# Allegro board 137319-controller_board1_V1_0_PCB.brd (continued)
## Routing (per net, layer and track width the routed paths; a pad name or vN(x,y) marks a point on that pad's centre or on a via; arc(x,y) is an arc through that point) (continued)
PTC31: length 7.4
  TOP w0.127: 27.3,42.42 27.83,42.95 27.83,43.85 U2.W5
  TOP w0.152: D1.1 25.15,38.99 25.15,40.26 27.3,42.42
PTD0: length 5.5
  TOP w0.127: 37.84,42.42 U2.Y17
  TOP w0.152: R20.1 39.62,40.01 37.84,41.79 37.84,42.42
PTD4: length 7.3
  TOP w0.127: U2.W19 39.85,43.85 40.61,43.85 41.27,43.18
  TOP w0.152: 41.27,43.18 41.78,42.67 41.78,39.62 R21.1
PTD5: length 6.6
  TOP w0.127: 41.27,43.69 40.71,44.25 U2.W20
  TOP w0.152: 41.27,43.69 42.16,42.8 R18.1
PTD7: length 11.3
  TOP w0.127: U2.V19 39.85,45.46 40.51,45.46 41.27,44.7
  TOP w0.152: R22.1 46.1,41.15 44.45,42.8 43.17,42.8 41.27,44.7
PTD8: length 10.6
  TOP w0.127: U2.U17 37.84,45.85 v1(38.24,45.45)
  BOTTOM w0.152: v1(38.24,45.45) 38.24,45.33 39.37,44.2 41.15,44.2 43.56,41.78 43.56,38.99 R23.1
RCON0: length 19.5
  TOP w0.127: U2.M20 40.47,49.85 41.2,49.85 41.27,49.78
  TOP w0.152: RA2.6 44.35,45.09 44.3,45.03 43.36,45.03 v2(42.8,45.59) 41.91,46.48 41.91,49.15 41.27,49.78 ; 50.52,44.83 v2(51.69,44.83)
  ART04 w0.127: v2(42.8,45.59) 43.43,44.96 44.96,44.96 45.89,45.89 50.63,45.89 v2(51.69,44.83)
RCON1: length 21
  TOP w0.127: 41.27,49.15 40.98,49.45 39.85,49.45 U2.M19
  TOP w0.152: S1.7 v2(51.69,43.56) ; 41.27,49.15 41.53,48.9 41.53,45.34 v2(42.8,44.07) 43.36,44.63 44.3,44.63 44.35,44.58 44.98,44.58
  ART04 w0.127: v2(51.69,43.56) 46.1,43.56 45.05,44.62 43.35,44.62 v2(42.8,44.07)
RCON2: length 21.8
  TOP w0.127: U2.M17 37.84,49.85 v1(38.24,49.45)
  TOP w0.152: S1.8 v2(51.69,42.29) ; RA2.8 v2(44.07,44.07)
  ART04 w0.127: v1(38.24,49.45) 38.64,49.05 40.86,49.05 41.91,48.01 41.91,44.19 42.66,43.43 43.43,43.43 v2(44.07,44.07) 44.83,44.07 45.72,43.18 50.8,43.18 v2(51.69,42.29)
RCON3: length 9.4
  TOP w0.127: U2.M16 v1(37.44,49.45)
  TOP w0.152: RA3.5 v2(44.07,51.18)
  BOTTOM w0.127: v1(37.44,49.45) 37.84,49.85 37.84,50.54 38.1,50.8 41.27,50.8
  BOTTOM w0.152: v2(44.07,51.18) 43.43,50.55 41.66,50.55 41.4,50.8 41.27,50.8
RCON4: length 9
  TOP w0.127: U2.L16 v1(37.44,50.25)
  TOP w0.152: RA3.6 44.35,50.67 44.3,50.62 43.44,50.62 v2(42.89,51.18)
  BOTTOM w0.127: 41.27,51.18 37.97,51.18 37.44,50.65 v1(37.44,50.25)
  BOTTOM w0.152: 41.27,51.18 42.67,51.18 42.67,51.18 v2(42.89,51.18)
RCON5: length 24
  TOP w0.127: U2.L17 37.84,50.65 v1(38.24,50.25)
  TOP w0.152: RA1.7 44.35,47.37 44.3,47.42 43.36,47.42 v2(42.8,46.86) ; S1.3 v2(51.69,48.64)
  ART04 w0.127: v2(51.69,48.64) 51.65,48.68 46.27,48.68 45.09,47.5 43.43,47.5 v2(42.8,46.86)
  BOTTOM w0.127: v1(38.24,50.25) 38.64,49.85 39.3,49.85 39.75,49.4 41.27,49.4
  BOTTOM w0.152: v2(42.8,46.86) 43.56,47.62 44.32,47.62 44.7,48.01 44.7,48.64 43.94,49.4 41.27,49.4
RCON6: length 19.8
  TOP w0.127: v1(39.04,50.25) 38.64,50.65 U2.L18
  TOP w0.152: 50.52,47.37 v2(51.69,47.37) ; RA1.8 v2(44.07,46.86)
  ART04 w0.127: v2(44.07,46.86) 44.36,46.57 50.89,46.57 v2(51.69,47.37)
  BOTTOM w0.127: v1(39.04,50.25) 39.28,50.25 39.74,49.78 41.27,49.78
  BOTTOM w0.152: v2(44.07,46.86) 45.09,47.88 45.09,48.9 44.2,49.78 41.27,49.78
RCON7: length 20.1
  TOP w0.127: v1(40.64,50.25) 40.24,50.65 U2.L20
  TOP w0.152: RA2.5 v2(44.07,45.59) ; S1.5 v2(51.69,46.1)
  ART04 w0.127: v2(51.69,46.1) 51.56,46.23 45.72,46.23 45.09,45.59 v2(44.07,45.59)
  BOTTOM w0.127: 41.27,50.16 40.73,50.16 v1(40.64,50.25)
  BOTTOM w0.152: 41.27,50.16 44.58,50.16 45.47,49.28 45.47,46.99 v2(44.07,45.59)
RCON8: length 5.3
  TOP w0.127: 41.27,51.45 U2.K20
  TOP w0.152: 41.27,51.45 41.51,51.45 42.8,50.16 RA3.7
RCON9: length 6.3
  TOP w0.127: U2.K19 39.84,51.05 41.27,51.05
  TOP w0.152: 41.27,51.05 42.67,49.66 RA3.8
RCON10: length 10.6
  TOP w0.127: U2.K18 38.64,51.45 v1(39.04,51.85)
  TOP w0.152: RA4.5 v2(44.07,56.77)
  ART04 w0.127: v1(39.04,51.85) 39.44,52.25 41.07,52.25 41.66,52.83 41.66,53.59 42.67,54.61 43.05,54.61 43.43,54.99 43.43,56.13 v2(44.07,56.77)
  BOTTOM w0.152: R1.1 v2(44.07,56.77)
RCON11: length 15
  TOP w0.127: v1(34.24,59.05) 33.84,58.65 U2.A12
  TOP w0.152: v2(42.8,59.18) 42.8,56.77 43.36,56.21 44.3,56.21 44.35,56.26 RA4.6
  BOTTOM w0.127: 35.38,60.2 v1(34.24,59.05)
  BOTTOM w0.152: 35.38,60.2 35.51,60.33 41.66,60.33 v2(42.8,59.18)
RCON12: length 11.2
  TOP w0.127: v1(38.24,52.65) 37.84,52.25 U2.J17
  TOP w0.152: RA4.7 44.35,55.75 44.3,55.8 43.36,55.8 v2(42.8,55.24)
  ART04 w0.127: v2(42.8,55.24) 40.6,53.05 40,53.05 39.67,53.05 38.64,53.05 v1(38.24,52.65)
  BOTTOM w0.152: R2.1 44.58,55.88 43.43,55.88 v2(42.8,55.24)
RCON13: length 6.8
  TOP w0.127: U2.D19 39.44,56.25 v1(39.84,56.65)
  TOP w0.152: RA4.8 v2(44.07,55.24)
  BOTTOM w0.127: 41.27,55.88 40.9,56.25 40.24,56.25 v1(39.84,56.65)
  BOTTOM w0.152: 41.27,55.88 42.55,54.61 43.43,54.61 v2(44.07,55.24)
RCON14: length 10
  TOP w0.127: v1(39.84,57.45) 39.44,57.05 U2.C19
  TOP w0.152: RA5.5 v2(44.07,53.94)
  ART04 w0.127: v2(44.07,53.94) 44.83,54.7 44.83,56.9 44.41,57.32 42.51,57.32 42.37,57.45 v1(39.84,57.45)
RCON18: length 27
  TOP w0.127: U2.L4 27.84,50.25 v1(28.64,50.25)
  TOP w0.152: RA5.6 44.35,53.43 44.3,53.38 43.36,53.38 v2(42.8,53.94)
  ART03 w0.127: v2(42.8,53.94) 42.71,53.86 36.95,53.86 35.44,55.37 35.44,56.02 35.2,56.25 35.19,56.25 35.18,56.26 31.68,56.26 31.44,56.01 31.44,51.63 30.61,50.8 29.19,50.8 v1(28.64,50.25)
  BOTTOM w0.152: R3.1 44.58,53.34 43.4,53.34 v2(42.8,53.94)
RCON20: length 92.3
  TOP w0.152: v2(42.8,52.42) 43.36,52.98 44.3,52.98 44.35,52.93 RA5.7
  ART04 w0.127: v2(13.06,60.2) 13.06,62.48 11.56,63.98 11.56,65.88 10.79,66.64 10.79,77.34 12.95,79.5 36.83,79.5 38.61,77.72 42.93,77.72 48.64,72.01 48.64,52.7 48.01,52.07 46.23,52.07 45.34,52.96 44.3,52.96 44.3,52.96 43.84,52.96 43.84,52.96 43.34,52.96 v2(42.8,52.42)
  BOTTOM w0.152: R4.1 44.56,52.98 43.36,52.98 v2(42.8,52.42) ; U15.18 v2(13.06,60.2)
RCON21: length 17.2
  TOP w0.127: U2.A17 37.84,58.66 v1(37.44,59.05)
  TOP w0.152: RA5.8 v2(44.07,52.42)
  ART04 w0.127: v1(37.44,59.05) 37.84,58.65 37.84,51.69 38.22,51.31 41.53,51.31 42.04,51.82 43.47,51.82 v2(44.07,52.42)
  BOTTOM w0.152: v2(44.07,52.42) 44.07,52.32 R5.1
RCON22: length 37.7
  TOP w0.152: v2(25.78,39.88) 26.42,40.51 27.43,40.51 27.81,40.13 27.81,38.73 27.3,38.23 RA6.5
  ART03 w0.127: v2(10.92,60.2) 10.92,58.29 11.66,57.56 11.66,52.86 13.34,51.18 17.53,51.18 18.92,49.78 21.34,49.78 24,47.12 24,41.66 v2(25.78,39.88)
  BOTTOM w0.152: v2(10.92,60.2) 12.06,60.2 12.41,60.54 U15.17
RCON30: length 10.2
  TOP w0.127: v1(29.44,46.25) 29.84,46.65 U2.T7
  TOP w0.152: RA6.6 26.8,38.73 v2(27.05,38.99)
  BOTTOM w0.127: 29.84,42.42 29.84,45.85 v1(29.44,46.25)
  BOTTOM w0.152: v2(27.05,38.99) 29.84,41.78 29.84,42.42
RCON31: length 8.4
  TOP w0.127: v1(29.44,44.65) 29.84,45.05 U2.V7
  TOP w0.152: v2(27.05,39.88) 26.29,39.12 RA6.7
  BOTTOM w0.127: v1(29.44,44.65) 29.04,44.25 29.04,42.42
  BOTTOM w0.152: 29.04,42.42 29.04,41.87 v2(27.05,39.88)
RESET_B: length 59.7
  TOP w0.127: U2.T4 27.44,46.65 v1(27.04,46.25)
  TOP w0.152: U18.4 v2(20.83,31.31)
  ART03 w0.127: v2(21.21,46.23) 19.56,44.58 19.56,32.58 v2(20.83,31.31)
  ART04 w0.127: v2(12.83,64.9) 13.97,63.75 13.97,59.83 14.61,59.19 14.61,57.4 13.97,56.77 13.97,53.85 14.61,53.21 14.61,51.44 18.16,47.88 18.16,47.2 19.14,46.23 v2(21.21,46.23)
  BOTTOM w0.127: v1(27.04,46.25) 26.64,45.85 26.07,45.85 22.86,45.85
  BOTTOM w0.152: 13.71,64.9 v2(12.83,64.9) 12.45,65.28 J3.10 ; C34.1 R46.2 v2(21.21,46.23) 21.59,45.85 22.86,45.85
SAFE_MODE_EN_N: length 66
  TOP w0.127: v1(39.04,46.25) 38.64,46.65 U2.T18
  ART03 w0.127: v1(39.04,46.25) 39.44,46.65 41.06,46.65 41.78,47.37 41.78,48.9 42.42,49.53 45.47,49.53 46.1,50.16 47.75,50.16 48.28,50.69 48.28,64.5 47.62,65.15 47.62,76.71 44.58,79.76 36.2,79.76 30.99,84.96 30.99,86.49 30.48,87 27.01,87 J1.15
SDHC1_CD: length 8.4
  TOP w0.127: U2.V15 36.24,45.05 v1(36.64,44.65)
  BOTTOM w0.152: R60.1 R59.1 36.64,40.7 v1(36.64,44.65)
SDHC1_CLK: length 50.8
  TOP w0.152: CN1.5 9.82,22.18 10.54,21.46 17.52,21.46 U7.6 v2(17.85,22.86) ; 43.43,37.72 43.43,34.67 v2(40.64,31.88)
  ART04 w0.127: v2(17.85,22.86) 17.85,26.61 22.86,31.62 27.69,31.62 28.45,30.86 30.23,30.86 31.11,31.75 33.91,31.75 34.46,32.3 40.22,32.3 v2(40.64,31.88)
  BOTTOM w0.152: R56.2 v2(17.85,22.86)
SDHC1_CMD: length 62.6
  TOP w0.127: U2.R17 37.84,47.45 v1(38.24,47.05)
  TOP w0.152: CN1.3 8.68,19.98 9.4,20.7 18.99,20.7 19.75,21.46 U7.4 v2(19.75,22.86)
  ART04 w0.127: v2(19.75,22.86) 19.75,22.92 19.43,23.24 19.43,27.05 22.61,30.23 40.13,30.23 41.53,31.62 41.53,37.08 37.84,40.77 37.84,46.66 v1(38.24,47.05)
  BOTTOM w0.152: R55.2 v2(19.75,22.86)
SDHC1_DAT0: length 61.5
  TOP w0.127: U2.R19 v1(39.84,47.05)
  TOP w0.152: CN1.7 12.96,24.38 13.84,23.5 18.92,23.5 19.62,24.2 U8.1 v2(21.21,24.2)
  ART04 w0.127: v2(21.21,24.2) 20.57,24.83 20.57,26.23 23.42,29.08 40.77,29.08 42.67,30.99 42.67,33.78 43.43,34.54 43.43,37.08 41.53,38.99 41.53,43.43 41.15,43.81 41.15,45.75 v1(39.84,47.05)
  BOTTOM w0.152: R57.2 v2(21.21,24.2)
SDHC1_DAT1: length 59.3
  TOP w0.127: U2.R20 40.24,47.45 v1(40.64,47.05)
  TOP w0.152: CN1.8 12.78,25.48 14.35,27.05 18.8,27.05 19.75,26.1 U8.3 v2(21.21,26.1)
  ART04 w0.127: v2(21.21,26.1) 23.82,28.7 41.02,28.7 43.05,30.73 43.05,33.66 43.81,34.42 43.81,37.21 41.91,39.12 41.91,43.69 41.53,44.07 41.53,46.16 v1(40.64,47.05)
  BOTTOM w0.152: R58.2 v2(21.21,26.1)
SDHC1_DAT2: length 70.7
  TOP w0.127: U2.P20 40.24,48.25 v1(40.64,48.65)
  TOP w0.152: CN1.1 7.87,17.78 9.78,19.68 17.52,19.68 U7.1 R53.2 18.1,17.27 18.67,17.27 v2(18.8,17.14)
  ART04 w0.127: v1(40.64,48.65) 40.24,48.25 38.88,48.25 38.64,48.02 38.64,40.48 41.91,37.21 41.91,31.37 40.39,29.84 22.86,29.84 19.81,26.8 19.81,24.13 20.32,23.62 20.32,21.87 19.56,21.11 19.56,17.91 v2(18.8,17.14)
SDHC1_DAT3: length 69.7
  TOP w0.127: v1(39.04,47.85) 38.64,48.25 U2.P18
  TOP w0.152: CN1.2 8.21,18.88 9.65,20.32 19.18,20.32 19.75,19.75 U7.3 R54.2 v2(20.57,17.53)
  ART04 w0.127: v2(20.57,17.53) 19.94,18.16 19.94,20.95 20.7,21.72 20.7,23.88 20.19,24.38 20.19,26.54 23.11,29.46 40.64,29.46 42.25,31.08 42.25,37.38 41.15,38.48 41.15,43.18 39.44,44.89 39.44,47.45 v1(39.04,47.85)
SPI_CS0_FPGA: length 18.1
  TOP w0.152: 42.16,37.72 42.16,34.29 39.37,31.5 39.37,27.97 38.45,27.05 35.43,27.05 34.54,26.16 34.54,25.13 U11.A10
SPI_CS1_FPGA: length 18.3
  TOP w0.152: U11.A9 34.16,25.55 34.16,26.29 35.31,27.43 38.29,27.43 38.89,28.03 38.89,31.66 41.45,34.21 41.45,37.16 40.89,37.72
SPI_DIN_FPGA: length 17.5
  TOP w0.127: U2.V20 40.24,45.05 v1(40.64,44.65)
  TOP w0.152: R64.1 v2(35.18,30.86)
  ART03 w0.127: v2(35.18,30.86) 35.81,31.5 35.81,33.27 36.79,34.25 36.79,40.81 v1(40.64,44.65)
SPI_DOUT_FPGA: length 19.1
  TOP w0.152: R22.2 46.1,36.32 39.88,30.1 39.88,27.94 38.61,26.67 35.69,26.67 34.95,25.93 U11.A11
SPI_SCK_FPGA: length 18.2
  TOP w0.127: U11.B10 v1(34.55,24.34)
  BOTTOM w0.152: v1(34.55,24.34) 35.39,24.34 42.16,31.11 42.16,34.8 43.43,36.07 43.43,37.59 43.31,37.72
TCK_FPGA: length 31.5
  TOP w0.127: U11.G2 v1(27.35,20.34)
  TOP w0.152: U16.3 48.23,29.24 v2(48.9,28.57)
  ART04 w0.127: v1(27.35,20.34) 26.92,20.77 26.92,23.11 29.84,26.04 30.99,26.04 31.88,26.92 44.04,26.92 46.32,29.21 48.26,29.21 v2(48.9,28.57)
TDI_FPGA: length 26.2
  TOP w0.127: U11.F5 v1(29.75,21.14)
  TOP w0.152: U16.4 v2(47.58,28.57)
  ART04 w0.127: v2(47.58,28.57) 46.23,28.57 44.2,26.54 32.13,26.54 30.15,24.56 30.15,21.54 v1(29.75,21.14)
TDO_FPGA: length 21.4
  TOP w0.127: U11.F6 v1(30.55,21.14)
  TOP w0.152: U16.15 46.28,24.44 v2(45.21,23.37)
  ART04 w0.127: v1(30.55,21.14) 30.95,21.54 30.95,23.7 32.14,24.89 35.94,24.89 37.47,23.37 v2(45.21,23.37)
TMS_FPGA: length 30.8
  TOP w0.127: U11.G1 v1(26.55,20.34)
  TOP w0.152: U16.2 48.88,29.73 v2(48.9,29.72)
  ART04 w0.127: v2(48.9,29.72) 46.29,29.72 43.88,27.3 31.75,27.3 30.86,26.42 28.83,26.42 28.31,25.89 28.31,25.03 26.54,23.27 26.54,20.35 v1(26.55,20.34)
TRACE_D0: length 33.2
  TOP w0.127: v1(28.64,43.85) 28.24,43.45 U2.Y5
  ART04 w0.127: J3.14 7.87,57.28 7.87,53.59 14.48,46.99 17.41,46.99 19.06,45.34 22.35,45.34 23.44,44.25 28.24,44.25 v1(28.64,43.85)
TRACE_D1: length 32.3
  TOP w0.127: U2.Y6 29.04,43.45 v1(28.64,43.05)
  ART04 w0.127: J3.16 7.49,55.12 7.49,53.34 14.73,46.1 14.73,44.45 15.41,43.78 25.18,43.78 25.53,43.43 28.26,43.43 v1(28.64,43.05)
TRACE_D2: length 33.7
  TOP w0.127: U2.V6 v1(28.64,45.45)
  ART04 w0.127: v1(28.64,45.45) U2.V6 29.04,42.76 28.83,42.55 20.57,42.55 19.68,43.43 15.24,43.43 14.35,44.32 14.35,45.85 5.08,55.12 J3.18
TRACE_D3: length 33.9
  TOP w0.127: v1(29.44,45.45) 29.04,45.85 U2.U6
  ART04 w0.127: v1(29.44,45.45) 29.84,45.05 29.84,42.67 29.33,42.16 20.45,42.16 19.56,43.05 14.99,43.05 13.97,44.07 13.97,45.72 7.11,52.58 4.95,52.58
TRACECK: length 30
  TOP w0.127: U2.L3 26.64,50.65 v1(26.24,50.25)
  ART03 w0.127: v1(26.24,50.25) 26.15,50.16 19.05,50.16 17.65,51.56 17.65,52.07 17.02,52.7 14.86,52.7 12.06,55.5 12.06,57.91 11.56,58.42 11.56,60.45 10.54,61.47 6.22,61.47 J3.12
UART_RX0_DEBUG: length 33.6
  TOP w0.127: U2.D14 v1(35.04,56.65)
  ART03 w0.127: v1(35.04,56.65) 35.6,56.65 36.31,57.36 36.31,65.01 36.58,65.28 36.58,78.49 30.08,84.98 30.08,85.92 J1.20
UART_RX1: length 64.8
  TOP w0.127: U2.Y18 38.64,42.42
  TOP w0.152: v2(40.39,40.39) 38.64,42.13 38.64,42.42
  ART03 w0.127: J1.24 39.48,80.52 44.83,80.52 48.39,76.96 48.39,65.41 49.02,64.77 49.02,44.83 44.58,40.39 v2(40.39,40.39)
UART_RX2: length 39.6
  TOP w0.127: v1(39.04,56.65) 38.64,56.25 U2.D18
  BOTTOM w0.127: 41.27,57.05 39.44,57.05 v1(39.04,56.65)
  BOTTOM w0.152: 41.27,57.05 42.45,57.05 43.43,58.04 43.43,66.29 42.8,66.93 41.02,66.93 38.35,69.6 38.35,83.22 36.99,84.58 36.99,87.01 J1.25
UART_RX3: length 88
  TOP w0.127: U11.J9 v1(33.75,17.94)
  ART03 w0.127: v1(33.75,17.94) 34.16,18.35 34.16,18.8 34.54,19.18 36.46,19.18 36.85,19.56 37.08,19.56 38.48,20.95 38.48,24.95 50.55,37.02 50.55,65.28 49.91,65.91 49.91,79.25 48.26,80.9 41.53,80.9 38.99,83.44 38.99,87.01 J1.27
UART_RX4: length 90.3
  TOP w0.127: U11.K10 v1(34.55,17.14)
  TOP w0.152: J1.29 41.01,86.99 41.01,85.59 41.59,85.01 41.61,85.01 41.78,84.84 44.96,84.84 46.23,83.57 v2(46.23,82.3)
  ART03 w0.127: v2(46.23,82.3) 46.86,82.93 48.9,82.93 52.45,79.38 52.45,63.88 53.21,63.12 53.21,37.59 40.01,24.38 40.01,20.32 37.67,17.98 36.76,17.98 36.32,17.54 34.94,17.54 34.55,17.15 v1(34.55,17.14)
UART_RX5: length 82.7
  TOP w0.127: U11.J10 v1(34.55,17.94)
  ART03 w0.127: v1(34.55,17.94) 34.95,18.34 36.24,18.34 36.25,18.34 36.32,18.34 36.55,18.57 36.55,18.64 36.55,18.64 36.55,18.9 36.78,19.14 37.17,19.14 38.86,20.83 38.86,24.8 50.93,36.86 50.93,65.41 50.29,66.04 50.29,79.38 48.39,81.28 44.05,81.28 42,83.33 J1.32
UART_RX6: length 83.6
  TOP w0.127: U11.H13 v1(36.95,18.74)
  ART03 w0.127: v1(36.95,18.74) 37.41,18.74 39.24,20.57 39.24,24.64 52.48,37.87 52.48,62.72 51.69,63.51 51.69,78.96 48.99,81.66 44.29,81.66 43.02,82.93 43.02,87.02 J1.33
UART_RX7: length 81.4
  TOP w0.127: U11.J12 v1(36.15,17.94)
  TOP w0.152: v2(48.13,82.3) 48.13,83.57 46.99,84.71 46.99,86.99 J1.37
  ART03 w0.127: v2(48.13,82.3) 48.99,82.3 52.07,79.22 52.07,63.63 52.83,62.87 52.83,37.72 39.62,24.51 39.62,20.45 37.49,18.31 36.73,18.31 36.35,17.94 v1(36.15,17.94)
UART_RX8: length 79.3
  TOP w0.127: U11.H8 v1(32.95,18.74)
  TOP w0.152: v2(48.51,79.12) 49.01,79.62 49.01,87.01 J1.39
  ART03 w0.127: v2(48.51,79.12) 49.15,78.49 49.15,65.66 49.78,65.02 49.78,37.33 37.72,25.27 37.72,21.21 36.2,19.68 33.9,19.68 v1(32.95,18.74)
UART_RX9: length 30.8
  TOP w0.127: U11.E12 v1(36.15,21.14)
  ART03 w0.127: J2.7 20.49,7.49 24,7.49 27.94,11.43 27.94,13.46 28.55,14.07 28.55,15.09 28.55,15.09 28.55,18.9 28.78,19.14 28.79,19.14 28.83,19.18 32.89,19.18 33.66,19.94 34.95,19.94 v1(36.15,21.14)
UART_RX10: length 21.5
  TOP w0.127: U11.L5 v1(29.75,17.14)
  ART03 w0.127: v1(29.75,17.14) 29.35,16.74 29.35,13.6 28.7,12.95 28.7,11.05 24.13,6.48 21.84,6.48 19.98,4.61 19.98,2.98 J2.10
UART_RX11: length 20.1
  TOP w0.127: U11.L4 v1(29.75,16.34)
  ART03 w0.127: J2.12 21.98,2.98 21.98,4.58 22.86,5.46 24.38,5.46 30.61,11.68 30.61,14.73 30.15,15.19 30.15,15.94 v1(29.75,16.34)
UART_RX12: length 15.6
  TOP w0.152: J2.16 26.01,3.01 26.01,5.15 30.1,9.24 30.1,14.39 U11.N4
UART_RX13: length 12.7
  TOP w0.152: U11.N5 30.48,14.81 30.48,9.08 27,5.6 J2.17
UART_RX14: length 14.3
  TOP w0.152: U11.N7 31.24,14.63 31.24,7.87 30.01,6.64 30.01,3.01 J2.20
UART_RX15: length 15.2
  TOP w0.127: U11.M9 33.76,15.53 33.76,14.22
  TOP w0.152: 33.76,14.22 33.76,8.74 32,6.99 32,3 J2.22
UART_RX16: length 14
  TOP w0.152: U11.N11 34.95,6.96 35.99,5.92 35.99,2.99 J2.26
UART_RX17: length 13
  TOP w0.127: U11.N8 v1(32.95,14.74)
  ART03 w0.127: v1(32.95,14.74) 37,10.69 J2.27
UART_RX18: length 16.6
  TOP w0.127: U11.M8 v1(32.95,15.54)
  ART03 w0.127: v1(32.95,15.54) 37.98,10.51 37.98,3.02 J2.30
UART_RX19: length 16.6
  TOP w0.152: U11.M13 36.96,15.53 36.96,9.44 41.99,4.41 41.99,2.99 J2.32
UART_RX_FROM_FPGA: length 24.7
  TOP w0.127: U2.M3 26.64,49.85 v1(26.24,49.45)
  TOP w0.152: R65.1 30.81,30.53 30.81,31.67 v2(29.97,32.51)
  ART03 w0.127: v2(29.97,32.51) 31.44,33.98 31.44,44.02 31.2,44.25 30.08,44.25 29.84,44.49 29.84,46.41 28,48.25 26.88,48.25 26.64,48.49 26.64,49.05 v1(26.24,49.45)
UART_TX0_DEBUG: length 27.9
  TOP w0.152: R25.1 38.93,65.21 38.93,65.72 v2(39.5,66.29)
  BOTTOM w0.152: J1.19 30.99,87.01 30.99,84.96 37.59,78.36 37.59,68.2 v2(39.5,66.29)
UART_TX1: length 67
  TOP w0.152: 39.62,37.72 40.13,37.72 40.26,37.85 40.26,39.12 40.94,39.8 40.94,40.84 v2(40.39,41.4)
  ART03 w0.127: v2(40.39,41.4) 41.02,40.77 44.42,40.77 48.68,45.03 48.68,64.6 48.01,65.28 48.01,76.83 44.7,80.14 37.86,80.14 J1.22
UART_TX2: length 26.3
  TOP w0.152: R24.1 v2(39.5,65.41)
  BOTTOM w0.152: v2(39.5,65.41) 40.13,66.04 40.13,66.93 37.97,69.09 37.97,81.85 34.99,84.84 34.99,87.01 J1.23
UART_TX3: length 89.5
  TOP w0.127: U11.K13 v1(36.95,17.14)
  TOP w0.152: J1.28 40.56,83.44 44.32,83.44 v2(44.94,84.06)
  ART03 w0.127: v1(36.95,17.14) 37.97,17.14 40.77,19.94 40.77,24.17 54.01,37.42 54.01,63.46 53.21,64.26 53.21,79.75 49.27,83.69 45.34,83.69 44.97,84.06 v2(44.94,84.06)
UART_TX4: length 88
  TOP w0.127: v1(36.15,17.14) 35.35,17.14 U11.K11
  TOP w0.152: v2(43.69,84.07) 41.4,84.07 40,85.48 J1.30
  ART03 w0.127: v2(43.69,84.07) 44.45,83.31 49.11,83.31 52.83,79.59 52.83,64.14 53.63,63.33 53.63,37.5 40.39,24.26 40.39,20.07 37.97,17.65 36.9,17.65 36.39,17.14 v1(36.15,17.14)
UART_TX5: length 85.1
  TOP w0.127: U11.L12 v1(36.15,16.34)
  ART03 w0.127: v1(36.15,16.34) 36.55,16.74 38.2,16.74 41.15,19.68 41.15,24 54.39,37.25 54.39,63.59 53.59,64.39 53.59,79.91 49.43,84.07 45.93,84.07 J1.34
UART_TX6: length 82.2
  TOP w0.127: U11.H9 v1(33.75,18.74)
  TOP w0.152: v2(47.37,79.12) 47.37,83.19 45.01,85.55 45.01,87.01 J1.35
  ART03 w0.127: v2(47.37,79.12) 48.01,79.76 48.86,79.76 49.53,79.09 49.53,65.79 50.16,65.15 50.16,37.18 38.1,25.11 38.1,21.12 36.79,19.81 36.74,19.81 36.36,19.43 34.29,19.43 33.75,18.89 v1(33.75,18.74)
UART_TX7: length 81.2
  TOP w0.127: U11.L13 v1(36.95,16.34)
  ART03 w0.127: v1(36.95,16.34) 38.31,16.34 41.53,19.56 41.53,23.88 54.74,37.08 54.74,63.88 53.98,64.64 53.98,80.02 J1.38
UART_TX8: length 73.6
  TOP w0.127: v1(36.95,21.94) 37.35,21.54 37.35,20.58 37.1,20.33 36.14,20.33 U11.G12
  TOP w0.152: J1.40 50,79.46 v2(48.51,77.98)
  ART03 w0.127: v2(48.51,77.98) 48.77,77.72 48.77,65.53 49.4,64.9 49.4,37.49 37.35,25.44 37.35,22.34 v1(36.95,21.94)
UART_TX9: length 32.2
  TOP w0.127: U11.F12 v1(35.35,21.14)
  ART03 w0.127: J2.5 19,8 23.88,8 27.56,11.68 27.56,13.59 27.75,13.78 27.75,18.73 28.57,19.56 32.77,19.56 33.35,20.15 33.35,20.5 33.59,20.74 34.95,20.74 v1(35.35,21.14)
UART_TX10: length 17.9
  TOP w0.127: U11.M4 v1(28.95,15.54)
  ART03 w0.127: v1(28.95,15.54) 28.95,13.84 28.32,13.21 28.32,11.18 24.13,6.99 21.21,6.99 19,4.78 J2.9
UART_TX11: length 17.2
  TOP w0.127: U11.M5 v1(29.75,15.54)
  ART03 w0.127: J2.11 21,4.62 22.35,5.97 24.26,5.97 29.55,11.26 29.56,11.26 29.88,11.58 29.88,11.6 30.23,11.94 30.23,14.61 29.75,15.08 v1(29.75,15.54)
UART_TX12: length 19.2
  TOP w0.127: U11.K5 v1(30.55,17.14)
  ART03 w0.127: J2.14 24,3 24,4.45 30.95,11.39 30.95,15.7 30.55,16.1 v1(30.55,17.14)
UART_TX13: length 18.1
  TOP w0.127: U11.J5 v1(29.75,17.94)
  ART03 w0.127: v1(29.75,17.94) 30.15,17.54 30.72,17.54 30.95,17.3 30.95,16.17 31.37,15.75 31.37,10.37 J2.15
UART_TX14: length 11.9
  TOP w0.152: J2.19 29,7.06 30.86,8.92 30.86,15.05 U11.N6
UART_TX15: length 14.2
  TOP w0.127: U11.K6 v1(31.35,17.14)
  ART03 w0.127: J2.21 31.75,4.75 31.75,16.74 v1(31.35,17.14)
UART_TX16: length 18
  TOP w0.127: U11.J7 v1(31.35,17.94)
  ART03 w0.127: v1(31.35,17.94) 32.26,17.03 32.26,13.72 33.98,12 33.98,2.98 J2.24
UART_TX17: length 13.3
  TOP w0.127: 32.64,14.22 32.14,14.72 32.14,15.55 U11.M7
  TOP w0.152: v2(32.89,13.97) 32.64,14.22
  ART03 w0.127: v2(32.89,13.97) 35,11.86 J2.25
UART_TX18: length 19.5
  TOP w0.127: U11.J6 v1(30.55,17.94)
  ART03 w0.127: v1(30.55,17.94) U11.J6 32.08,18.34 33.35,17.07 33.35,15.93 39,10.28 J2.29
UART_TX19: length 13.5
  TOP w0.152: U11.N12 35.56,14.95 35.56,9.44 J2.31
UART_TX_TO_FPGA: length 44.9
  TOP w0.127: U11.A7 31.75,25.91 31.88,26.04
  TOP w0.152: v2(25.91,32.77) 26.29,33.15 32.51,33.15 33.4,32.26 33.4,30.43 33.27,30.3 33.27,27.43 31.88,26.04
  ART03 w0.127: v2(25.91,32.77) 25.15,33.53 25.15,39.88 23.62,41.4 23.62,46.99 21.97,48.64 17.14,48.64 16.38,49.4 v2(16.38,50.55)
  BOTTOM w0.152: v2(16.38,50.55) 16.38,52.32 16.89,52.83 R28.1
USB0_DN: length 64.6
  TOP w0.15: v1(31.04,46.25) 31.44,46.65 U2.T9
  ART04 w0.13: J2.2 12,3 12,4.51 12.83,5.34 12.83,10.13 15.11,12.41 15.11,27.56 16.64,29.08 16.64,30.86 20.7,34.92 34.16,34.92 34.8,35.56 34.8,39.5 32.51,41.78 32.51,45.6 32.26,45.85 31.44,45.85 v1(31.04,46.25)
USB0_DP: length 64.6
  TOP w0.15: U2.T10 32.24,46.65 v1(31.84,46.25)
  ART04 w0.13: J2.4 14,3 14,4.54 13.17,5.38 13.17,5.96 13.34,6.13 13.34,6.48 13.17,6.65 13.17,7 13.34,7.17 13.34,7.51 13.17,7.68 13.17,8.03 13.34,8.2 13.34,8.55 13.17,8.72 13.17,9.99 15.45,12.27 15.45,27.42 16.97,28.95 16.97,30.72 20.84,34.59 34.3,34.59 35.13,35.42 35.13,39.63 32.84,41.92 32.84,45.74 32.4,46.19 31.9,46.19 v1(31.84,46.25)
USB0_VBUS: length 58.9
  TOP w0.381: U2.W11 U2.Y11 33.04,41.93 32.26,41.15 v2(32.26,39.62) 32.26,38.86 C78.1
  ART04 w0.508: v2(32.26,39.62) 29.97,37.34 24.51,37.34 23.88,36.7 19.94,36.7 18.16,34.92 15.6,34.92 14.73,34.06 14.73,29.34 13.84,28.45 13.84,14.73 11,11.89 J2.1
  BOTTOM w0.381: C77.1 31.75,39.12 v2(32.26,39.62)
USB0_VBUS_EN_N: length 56.6
  TOP w0.127: U2.R3 26.64,47.45 v1(27.04,47.85)
  ART03 w0.127: v1(27.04,47.85) 27.44,47.46 27.44,42.76 26.45,41.78 26.45,32.42 25.49,31.46 25.49,15.28 26.42,14.35 26.42,11.18 23.75,8.51 18.13,8.51 14.02,4.41 14.02,2.98 J2.6
USB1_DN: length 24.7
  TOP w0.15: L1.2 14.59,40.41 14.85,40.14 14.85,39.08 15.19,38.74 15.46,38.74 v2(15.88,38.32) ; U2.V9 31.44,45.05 v1(31.04,44.65)
  ART04 w0.13: v1(31.04,44.65) 31.83,43.86 31.83,41.65 30.87,40.69 20.58,40.69 18.61,38.71 16.27,38.71 v2(15.88,38.32)
USB1_DP: length 24.6
  TOP w0.15: v1(31.04,43.85) 31.44,44.25 U2.W9 ; v2(15.88,39.44) 15.46,39.02 15.31,39.02 15.12,39.2 15.12,40.14 15.39,40.41 L1.3
  ART04 w0.13: v2(15.88,39.44) 16.27,39.05 18.47,39.05 20.45,41.02 22.19,41.02 22.45,41.27 22.71,41.27 22.97,41.02 23.23,41.02 23.48,41.27 23.75,41.27 24,41.02 24.27,41.02 24.52,41.27 24.78,41.27 25.04,41.02 25.3,41.02 25.56,41.27 25.82,41.27 26.07,41.02 26.34,41.02 26.59,41.27 26.86,41.27 27.11,41.02 27.37,41.02 27.63,41.27 27.89,41.27 28.15,41.02 28.41,41.02 28.66,41.27 28.93,41.27 29.18,41.02 29.45,41.02 29.7,41.27 29.97,41.27 30.22,41.02 30.73,41.02 31.5,41.78 31.5,43.69 31.33,43.85 v1(31.04,43.85)
USB1_VBUS: length 42.4
  TOP w0.381: C81.1 29.3,38.95 v2(29.3,39.62) ; U2.U9 31.44,45.85 v1(31.04,45.45) ; U2.W10 v1(31.84,44.65)
  ART04 w0.508: v2(29.3,39.62) 27.93,38.25 24.03,38.25 23.36,37.58 19.42,37.58 18.41,36.58 15.75,36.58 14.92,37.4 14.92,39.31 12.45,41.78 v2(12.45,46.23)
  BOTTOM w0.381: C80.1 29.72,39.2 v2(29.3,39.62) 29.34,39.66 29.34,40.13 31.84,42.63 v1(31.84,44.65) v1(31.04,45.45)
  BOTTOM w0.635: FB4.2 v2(12.45,46.23) ; v2(12.45,46.23) U9.7 ; v2(12.45,46.23) v2(11.18,46.23) U9.6
USB1_VBUS_EN_N: length 27.7
  TOP w0.127: U2.R4 27.44,47.45 27.05,47.06 23.57,47.06 v1(23.11,46.61)
  ART03 w0.127: v1(23.11,46.61) 22.95,46.77 20.74,46.77 19.18,45.21 19.18,42.16 17.49,40.47 17.49,39.2 16.64,38.35 16.64,36.83 15.58,35.78 11.85,35.78 11.3,36.32 v2(9.14,36.32)
  BOTTOM w0.254: R62.2 v2(9.14,36.32)
USB_N: length 18.4
  TOP w0.15: v2(15.88,45.5) 15.46,45.08 15.19,45.08 14.85,44.74 14.85,43.68 14.59,43.41 L1.1 ; v2(11.43,42.04) 11.43,42.8 11.12,43.11 U10.1 9.08,43.11 8.27,42.3 7.11,42.3 J5.2
  BOTTOM w0.15: v2(15.88,45.5) 15.71,45.33 15.13,45.33 14.73,44.94 14.73,41.91 14.22,41.4 12.83,41.4 12.35,41.88 11.59,41.88 v2(11.43,42.04)
USB_P: length 18.4
  TOP w0.15: v2(11.43,41.19) 11.4,41.21 U10.3 9.06,41.21 8.24,42.03 7.11,42.03 J5.3 ; v2(15.88,44.38) 15.46,44.8 15.31,44.8 15.12,44.62 15.12,43.68 15.39,43.41 L1.4
  BOTTOM w0.15: v2(15.88,44.38) 15.88,44.71 15.53,45.06 15.24,45.06 15.01,44.83 15.01,44.47 15.24,44.24 15.24,44.02 15.01,43.79 15.01,43.57 15.24,43.34 15.24,43.12 15.01,42.89 15.01,42.67 15.24,42.44 15.24,42.22 15.01,41.99 15.01,41.8 14.34,41.13 13.99,41.13 13.75,40.89 13.54,40.89 13.31,41.13 12.71,41.13 12.24,41.6 11.78,41.6 11.43,41.25 v2(11.43,41.19)
VREF_3V3: length 6.8
  TOP w0.381: FB3.1 C84.1 21.72,45.21 22.48,44.45 24.84,44.45 U2.W1
VREF_DDR3: length 34.3
  TOP w0.381: v1(28.64,54.25) 28.24,53.85 U2.G5 ; U3.M8 v1(30.51,73.25) ; U3.H1 v1(26.51,67.65) ; v2(20.7,61.98) 20.19,61.98 C5.1
  BOTTOM w0.381: 24.51,54.99 22.99,56.52 20.83,56.52 19.81,57.53 R9.1 C4.1 C3.2 R8.2 20.57,62.1 v2(20.7,61.98) 23.62,61.98 26.51,64.86 v1(26.51,67.65) 27.18,68.32 27.18,70.23 27.56,70.61 29.59,70.61 30.51,71.53 v1(30.51,73.25) 30.51,74.96 C6.1
XTAL_MAIN: length 15.9
  TOP w0.127: 35.81,42.42 35.05,43.19 35.05,43.85 U2.W13
  TOP w0.152: 35.81,42.42 37.34,40.89 R42.1 C30.1 38.86,38.73 39.04,38.56 39.04,36.4 40.13,35.31 40.13,33.66 39.79,33.32 Y1.3
N2153652: length 7.7
  TOP w0.254: U14.12 11.57,75.43 ; U14.10 12.57,75.43 ; U14.11 12.07,75.43
  TOP w0.381: R86.1 8.38,75.56 9.14,76.33 11.3,76.33
N2153712: length 3.4
  TOP w0.254: U14.5 v2(14.73,72.27)
  BOTTOM w0.381: v2(14.73,72.27) 15.74,72.27 R89.1 R88.2
N2153966: length 2.1
  TOP w0.152: v2(13.72,75.18) 13.21,75.18 13.07,75.05 U14.9
  BOTTOM w0.152: C114.1 13.72,74.42 v2(13.72,75.18)
N2153998: length 2.6
  TOP w0.254: U14.1 11.57,70.62 ; U14.2 12.07,70.62 ; U14.3 12.57,70.62
N2154070: length 2.4
  TOP w0.152: U14.4 13.07,71.13 v2(13.46,70.74)
  BOTTOM w0.152: v2(13.46,70.74) 12.95,70.74 12.7,70.99 R87.1
N2154096: length 1.4
  TOP w0.152: U14.13 R86.2
N2191397: length 9.5
  TOP w0.127: U2.U4 27.44,45.85 v1(27.04,45.45)
  BOTTOM w0.127: v1(27.04,45.45) 26.64,45.05 26.64,43.28 25.78,42.42
  BOTTOM w0.152: R91.1 23.24,39.88 25.78,42.42
N2191403: length 7.4
  TOP w0.127: v1(27.04,43.85) 27.44,44.25 U2.W4
  BOTTOM w0.152: R92.1 25.15,38.86 25.15,40.13 27.04,42.03 v1(27.04,43.85)
N2191409: length 8
  TOP w0.127: v1(27.84,44.65) 28.24,45.05 U2.V5
  BOTTOM w0.152: v1(27.84,44.65) 27.56,44.37 27.56,41.78 26.42,40.64 26.42,38.73 R93.1
N2191945: length 11.5
  TOP w0.127: U2.W3 26.64,44.25 v1(26.24,43.85)
  TOP w0.152: D2.3 22.01,38.64 22.37,39.01 v2(22.37,39.98)
  BOTTOM w0.127: v1(26.24,43.85) 24.8,42.42
  BOTTOM w0.152: R40.1 C32.1 22.37,38.37 v2(22.37,39.98) 24.8,42.42
N2191949: length 8.3
  TOP w0.127: 22.86,43.85 25.44,43.85 25.84,44.25 U2.W2
  TOP w0.152: D3.3 v2(21.21,43.18) 21.88,43.85 22.86,43.85
  BOTTOM w0.152: v2(21.21,43.18) R39.1 C29.1
N2191953: length 10
  TOP w0.152: D4.3 v2(21.21,40.01) 21.84,40.64 24,40.64 25.84,42.48 U2.Y2
  BOTTOM w0.152: C33.1 R38.1 21.08,39.88 v2(21.21,40.01)
N2192059: length 7.1
  TOP w0.152: U2.Y4 23.75,39.76 23.75,38.61 R90.1
N2281272: length 7.1
  TOP w0.254: R51.2 13.72,34.37 D5.2 13.38,34.71 SW1.1 11.94,34.27 11.94,31 SW1.2
N2281444: length 3.2
  TOP w0.152: U18.1 v2(15.79,33.21)
  BOTTOM w0.152: R50.1 R52.1 15.98,33.02 v2(15.79,33.21)
N2284326: length 1.6
  TOP w0.381: U4.C3 v1(39.89,75.46)
  BOTTOM w0.381: v1(39.89,75.46) 39.4,75.46 R15.2
N2287958: length 13.4
  TOP w0.127: U2.R16 v1(37.44,47.05)
  TOP w0.152: v2(42.8,41.4) 42.8,40.13 43.43,39.5 R19.2
  BOTTOM w0.127: 41.27,42.55 38.23,42.55 37.84,42.93 37.84,46.65 v1(37.44,47.05)
  BOTTOM w0.152: 41.27,42.55 41.66,42.55 v2(42.8,41.4)
N2289519: length 8.3
  BOTTOM w0.508: U9.5 9.91,43.43 10.29,43.05 12.74,43.05 13.22,43.53 13.22,43.53 13.72,44.03 U9.8 R61.1
N2289539: length 5
  BOTTOM w0.381: U9.3 R63.2 R62.1 U9.4
N2296270: length 2.5
  BOTTOM w0.152: U15.1 R6.1
N2296455: length 2.3
  BOTTOM w0.152: R7.1 U15.19
N2319696: length 2.3
  TOP w0.508: U5.1 51.85,58.2 ; U5.2 51.93,59.45
N2331782: length 5.6
  TOP w0.381: U11.K9 v1(33.75,17.14) ; U11.K4 v1(28.95,17.14) ; U11.D4 v1(28.95,22.74) ; U11.D10 v1(34.55,22.74) ; U11.D3 v1(28.15,22.74)
  BOTTOM w0.381: C103.1 28.14,22.73 v1(28.15,22.74) ; C104.1 34.42,16.47 v1(33.75,17.14) ; v1(34.55,22.74) 34.56,22.73 C102.1
  vias: v2(24,18.92) v2(24,18.03)
N2337623: length 7.2
  TOP w0.127: U11.C4 v1(28.95,23.54)
  TOP w0.152: R79.2 v2(26.04,28.07)
  BOTTOM w0.127: 28.55,24.66 28.55,23.94 v1(28.95,23.54)
  BOTTOM w0.152: v2(26.04,28.07) 26.04,27.18 28.55,24.66
N2337645: length 6.8
  TOP w0.127: v1(30.55,23.54) 30.15,23.14 U11.C5
  TOP w0.152: R80.2 28.57,28.45 v2(29.97,27.05)
  BOTTOM w0.127: 30.15,26.04 30.15,23.94 v1(30.55,23.54)
  BOTTOM w0.152: v2(29.97,27.05) 30.15,26.87 30.15,26.04
N2337651: length 8.6
  TOP w0.127: U11.E7 v1(31.35,21.94)
  TOP w0.152: R81.2 v2(33.91,28.07)
  BOTTOM w0.127: 32.15,26.04 32.15,22.74 v1(31.35,21.94)
  BOTTOM w0.152: 32.15,26.04 32.15,26.31 v2(33.91,28.07)
N2338140: length 8.7
  TOP w0.127: U11.E5 v1(29.75,21.94)
  TOP w0.152: v2(27.18,28.07) 27.3,28.19 R82.2
  BOTTOM w0.127: 29.35,24.63 29.35,22.34 v1(29.75,21.94)
  BOTTOM w0.152: v2(27.18,28.07) 27.18,26.8 29.35,24.63
N2350524: length 2.8
  TOP w0.152: D1.2 v2(24.51,35.56)
  BOTTOM w0.152: R37.2 v2(24.51,35.56)
N2353252: length 7.5
  TOP w0.127: U11.D6 v1(30.55,22.74)
  TOP w0.152: D8.1 v2(29.97,28.07)
  BOTTOM w0.127: 30.95,26.04 30.95,23.14 v1(30.55,22.74)
  BOTTOM w0.152: v2(29.97,28.07) 30.95,27.09 30.95,26.04
N2353538: length 9.1
  TOP w0.127: U11.D8 v1(32.95,22.74)
  TOP w0.152: R77.2 v2(36.45,28.07)
  BOTTOM w0.127: v1(32.95,22.74) 32.51,23.18 32.51,24.64 33.15,25.27 34.04,25.27
  BOTTOM w0.152: v2(36.45,28.07) 36.45,27.69 34.04,25.27
N2353540: length 7.3
  TOP w0.127: U11.B9 v1(33.75,24.34)
  TOP w0.152: R76.2 v2(37.72,28.07)
  BOTTOM w0.152: v1(33.75,24.34) 34.56,25.15 35.43,25.15 37.72,27.43 v2(37.72,28.07)
N2361317: length 4.5
  TOP w0.254: U17.3 42.99,10.98 43.43,11.43 R72.1 C94.1 R70.1
N2361377: length 7.1
  TOP w0.254: R72.2 D7.2 46.27,9.99 SW2.1 47.75,10.43 47.75,13.7 SW2.2
N2361557: length 3.4
  TOP w0.152: v2(41.27,9.27) 41.09,9.46 U17.1
  BOTTOM w0.152: R71.1 R73.1 v2(41.27,9.27)
N2361860: length 1.8
  TOP w0.152: X1.3 41.61,20.02 41.02,19.43
N2361916: length 5.2
  TOP w0.381: X1.1 44.88,18.41 C91.1 ; X1.1 X1.4 ; X1.1 FB5.1
N2362456: length 6.1
  TOP w0.127: U11.M3 28.14,16.35 26.54,16.35
  TOP w0.152: 26.54,16.35 26.12,16.35 24.64,14.86 D6.1
N2362502: length 1.4
  TOP w0.152: D6.2 21.72,13.46
N2363039: length 4.8
  TOP w0.127: 30.95,26.04 U11.A6
  TOP w0.152: 30.95,26.04 30.95,26.25 31.88,27.18 31.88,28.45 R65.2
N2363108: length 5.3
  TOP w0.152: R64.2 35.18,28.07 33.78,26.67 33.78,25.97 U11.A8
N2364591: length 5.7
  TOP w0.127: 31.35,26.04 31.35,24.34 U11.B6
  TOP w0.152: R66.2 32.64,27.43 31.35,26.14 31.35,26.04
N23532460: length 2.4
  TOP w0.152: D8.2 v2(29.97,31.5)
  BOTTOM w0.152: R78.2 v2(29.97,31.5)

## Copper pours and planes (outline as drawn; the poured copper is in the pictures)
GND on TOP: 56.01,20.19 56.01,28.7 56.52,29.21 56.52,31.62 56.01,32.13 56.01,33.02 55.5,33.53 47.37,33.53 46.74,34.16 46.74,39.24 46.61,39.37 46.61,51.31 47.12,51.82 47.12,57.15 47.37,57.4 47.88,57.4 48.13,57.15 54.1,57.15 54.36,57.4 54.36,58.04 54.48,58.17 57.02,58.17 57.28,58.42 57.28,61.34 53.34,65.28 53.34,71.37 50.8,73.91 50.8,89.28 50.93,89.41 59.18,89.41 59.44,89.15 59.44,0.89 59.05,0.51 42.55,0.51 42.29,0.76 42.29,5.08 41.27,6.1 41.27,7.75 41.59,8.06 41.59,9.46 41.78,9.65 43.69,9.65 44.7,10.67 45.34,10.67 45.47,10.54 45.47,9.27 45.97,8.76 48.64,8.76 49.02,9.14 49.02,14.22 46.74,16.51 46.74,20.07 46.86,20.19 ; 1 cut-out
GND on TOP: 23.62,28.57 25.02,28.57 25.15,28.45 25.15,26.67 25.02,26.54 23.62,26.54 23.5,26.67 23.5,28.45
GND on TOP: outline of 102 points within 0.51,0.51 36.96,89.41
GND on TOP: 27.69,13.08 29.84,13.08 29.97,12.95 29.97,11.43 29.84,11.3 27.69,11.3 27.56,11.43 27.56,12.95
GND on TOP: 15.62,73.03 15.62,70.61 15.75,70.48 18.03,70.48 18.16,70.61 18.16,73.03 18.03,73.15 15.75,73.15
GND on TOP: 21.46,17.27 23.37,17.27 23.5,17.14 23.5,15.88 23.37,15.75 21.46,15.75 21.34,15.88 21.34,17.14
GND on TOP: 14.48,78.99 14.48,77.85 14.73,77.6 14.73,75.95 14.86,75.82 17.14,75.82 17.27,75.95 17.27,78.99 17.14,79.12 14.61,79.12
GND on TOP: 54.48,58.17 56.39,58.17 56.52,58.04 56.52,56.77 56.39,56.64 54.48,56.64 54.36,56.77 54.36,58.04
GND on BOTTOM: 15.49,19.81 25.53,19.81 25.65,19.68 25.65,13.84 26.54,12.95 40.26,12.95 40.51,12.7 40.51,8.89 40.77,8.64 43.56,8.64 44.58,9.65 44.58,15.11 42.55,17.14 42.55,33.27 45.97,36.7 45.97,48.64 46.23,48.9 47.5,48.9 48.26,49.66 48.26,63.63 50.29,65.66 58.67,65.66 59.44,64.9 59.44,0.89 59.05,0.51 0.76,0.51 0.51,0.76 0.51,89.15 0.76,89.41 26.67,89.41 26.92,89.15 26.92,86.61 34.42,79.12 34.42,76.07 34.29,75.95 19.43,75.95 19.05,75.56 19.05,72.9 18.92,72.77 14.61,72.77 14.1,72.26 10.79,72.26 9.91,73.15 8.13,73.15 7.49,72.52 7.49,35.81 7.62,35.69 14.86,35.69 15.11,35.43 15.11,20.19 ; 2 cut-outs
GND on BOTTOM: 28.32,37.97 32.89,37.97 33.02,37.85 33.02,35.31 32.89,35.18 28.32,35.18 28.19,35.31 28.19,37.85
GND on GND02: 0.51,0.51 59.49,0.51 59.49,89.49 0.51,89.49
GND on POWER05: 1.02,1.02 1.02,50.69 1.25,50.93 6.88,50.93 7.49,50.31 7.49,16.15 9.53,14.12 9.53,1.12 9.42,1.02
GND on POWER05: 56.87,31.88 56.52,32.24 56.52,34.82 57.28,35.58 57.28,72.62 54.23,75.67 54.23,80.37 50.27,84.33 39.48,84.33 39.12,84.69 39.12,88.67 39.43,88.98 58.98,88.98 58.98,32.17 58.7,31.88
GND on POWER05: 16.62,1.02 16.26,1.38 16.26,12.09 16.87,12.7 22.12,12.7 26.82,8 46.71,8 48.01,9.29 48.01,17.17 52.2,21.36 52.2,27.58 53.06,28.45 58.7,28.45 58.98,28.16 58.98,1.02 ; 3 cut-outs
VCC on TOP: 14.73,80.01 14.61,79.88 11.3,79.88 11.18,80.01 11.18,86.61 11.3,86.74 14.61,86.74 14.73,86.61
VCC on BOTTOM: 13.34,49.28 13.34,47.62 13.46,47.5 14.99,47.5 15.11,47.62 15.11,49.28 14.99,49.4 13.46,49.4
VCC on ART04: 49.53,78.87 49.53,68.07 50.16,67.44 56.26,67.44 56.52,67.69 56.52,69.72 56.39,69.85 52.45,69.85 52.07,70.23 52.07,80.14 50.16,82.04 45.85,82.04 45.59,82.3 11.68,82.3 7.49,78.11 7.49,58.67 8.26,57.91 8.26,53.59 13.59,48.26 14.48,48.26 15.37,49.15 15.37,49.53 11.18,53.72 11.18,65.53 10.29,66.42 10.29,77.72 12.45,79.88 48.51,79.88
VCC_2V5_SDRAM on BOTTOM: 21.08,60.33 21.08,59.44 21.46,59.05 22.99,59.05 23.88,58.17 23.88,56.77 25.27,55.37 27.94,55.37 28.7,54.61 28.96,54.61 29.08,54.74 29.08,55.5 28.96,55.63 28.96,56.26 28.19,57.02 25.4,57.02 25.27,57.15 25.27,59.94 24.77,60.45 21.21,60.45
VCC_2V5_SDRAM on ART04: 32.13,55.37 32,55.24 28.7,55.24 28.07,54.61 28.07,52.45 27.94,52.32 26.42,52.32 26.29,52.45 26.29,56.26 26.67,56.64 32,56.64 32.13,56.52
VDD12 on TOP: 21.59,52.2 21.46,52.07 19.68,52.07 19.56,52.2 19.56,53.34 19.68,53.47 21.46,53.47 21.59,53.34
VDD12 on POWER05: 24.81,46.93 24.74,46.99 19.28,46.99 19.18,47.1 19.18,54.89 19.54,55.24 21.74,55.24 22.73,54.25 22.73,52.73 22.88,52.58 22.97,52.58 23.54,52.01 28.78,52.01 29.15,52.37 29.15,54.28 29.42,54.55 35.74,54.55 36.26,54.02 36.26,47.32 35.86,46.93
VDD15 on TOP: 15.62,52.32 18.41,52.32 18.54,52.2 18.54,51.18 18.41,51.05 15.62,51.05 15.49,51.18 15.49,52.2
VDD15 on TOP: 13.46,69.72 14.99,69.72 15.49,69.22 18.03,69.22 18.16,69.09 18.16,66.55 18.03,66.42 13.46,66.42 13.34,66.55 13.34,69.6
VDD15 on ART04: 17.02,67.18 17.27,66.93 17.27,58.8 17.91,58.17 17.91,51.69 17.65,51.44 15.24,51.44 14.99,51.69 14.99,59.31 14.35,59.94 14.35,66.93 14.61,67.18
VDD15 on POWER05: 23.7,52.39 23.24,52.85 23.24,54.46 21.95,55.75 19.54,55.75 19.18,56.11 19.18,56.87 18.39,57.66 17.63,57.66 17.4,57.89 17.4,63.99 16.74,64.64 14.84,64.64 12.45,67.03 12.45,77.24 13.19,77.98 35.71,77.98 36.32,77.36 36.32,62.46 33.66,59.8 33.66,59.33 33.72,59.27 33.72,55.2 33.45,54.93 29.26,54.93 28.77,54.43 28.77,52.53 28.62,52.39
VDD33 on TOP: 23.62,31.24 25.02,31.24 25.15,31.11 25.15,29.34 25.02,29.21 23.62,29.21 23.5,29.34 23.5,31.11
VDD33 on TOP: 54.61,59.94 54.61,58.55 54.74,58.42 56.52,58.42 56.64,58.55 56.64,59.94 56.52,60.07 54.74,60.07
VDD33 on TOP: 24.26,21.08 24.38,21.21 24.38,22.48 24.26,22.61 22.1,22.61 21.97,22.48 21.97,21.21 22.1,21.08
VDD33 on TOP: 27.05,12.83 27.05,11.68 26.92,11.56 24.77,11.56 24.64,11.68 24.64,12.83 24.77,12.95 26.92,12.95
VDD33 on ART04: 30.61,54.48 32.13,54.48 32.51,54.86 32.51,57.02 33.27,57.78 37.34,57.78 37.47,57.66 37.47,51.31 38.48,50.29 38.48,47.75 37.34,46.61 37.34,44.45 37.21,44.32 34.04,44.32 33.66,44.7 33.66,45.85 32.64,46.86 26.04,46.86 25.78,47.12 25.78,48.9 25.91,49.02 27.43,49.02 27.56,49.15 27.56,50.55 27.43,50.67 25.91,50.67 25.78,50.8 25.78,51.94 25.91,52.07 28.19,52.07
VDD33 on POWER05: 10.14,1.02 10.03,1.12 10.03,14.33 8,16.36 8,50.52 7.09,51.44 1.25,51.44 1.02,51.67 1.02,88.98 38.29,88.98 38.61,88.67 38.61,84.48 39.26,83.82 50.06,83.82 53.72,80.16 53.72,75.46 56.77,72.41 56.77,35.79 56.01,35.03 56.01,32.03 56.66,31.37 58.7,31.37 58.98,31.08 58.98,29.24 58.7,28.96 52.85,28.96 51.69,27.79 51.69,21.57 47.5,17.38 47.5,9.5 46.5,8.51 27.03,8.51 22.33,13.21 16.66,13.21 15.75,12.3 15.75,1.38 15.39,1.02 ; 1 cut-out
VREF_DDR3 on BOTTOM: 27.3,54.86 27.94,54.86 28.32,54.48 28.7,54.48 28.83,54.36 28.83,53.98 28.7,53.85 28.32,53.85 28.19,53.72 24.38,53.72 24.26,53.85 24.26,55.12 24.38,55.24 26.92,55.24
N2153652 on TOP: 13.46,75.95 13.46,77.6 14.1,78.23 14.1,79.12 13.97,79.25 11.3,79.25 11.18,79.12 11.18,75.44 11.3,75.31 12.83,75.31
N2153998 on TOP: 12.83,70.61 12.83,70.1 12.7,69.98 12.45,69.98 12.32,69.85 12.32,67.82 12.19,67.69 9.91,67.69 9.78,67.82 9.78,70.61 9.91,70.74 12.7,70.74
N2309411 on ART04: 0.89,58.93 1.14,58.67 3.56,58.67 3.81,58.93 3.81,63.12 4.32,63.63 5.97,63.63 7.11,64.77 7.11,78.74 11.18,82.8 50.42,82.8 52.58,80.64 52.58,70.48 52.83,70.23 56.52,70.23 56.64,70.36 56.64,72.77 54.61,74.8 54.61,81.79 51.44,84.96 7.37,84.96 0.89,78.49
N2319696 on TOP: 51.82,59.82 53.72,59.82 53.85,59.69 53.85,57.66 53.72,57.53 51.82,57.53 51.69,57.66 51.69,59.69
N2331782 on TOP: 22.1,20.32 22.1,17.91 22.23,17.78 24.26,17.78 24.38,17.91 24.38,19.18 23.62,19.94 23.62,20.32 23.5,20.45 22.23,20.45
N2331782 on ART04: 27.56,23.24 29.08,23.24 29.21,23.11 29.21,20.7 29.34,20.57 33.02,20.57 33.4,20.95 33.4,23.11 33.53,23.24 34.8,23.24 35.05,22.99 35.05,16.76 34.67,16.38 23.88,16.38 23.62,16.64 23.62,19.18 23.75,19.3 26.42,19.3 27.18,20.07 27.18,22.86

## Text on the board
Ref Des/Silkscreen Bottom: ID4 | ID5 | ID6
Ref Des/Silkscreen Top: ID3 | controller_board1_V1.0 | ID2 | ID1
DIMENSION: 0
BODY_CENTER: FIGURE | SIZE | 8.0 | 10.0 | 36.0 | 40.0 | 90.0 | 157.0 | DRILL CHART: TOP to BOTTOM | ALL UNITS ARE IN MILS | PLATED | QTY | 490 | 411 | 84 | 32 | 2 | 4
User.17: If the angle of PCB board outline is circular,please use this kind of break out area | If not use it,please delete it before you gerber out | If the angle of PCB board outline is right angle,please use this kind of break out area | AS usual,please use the 0.8MM stamp Via
